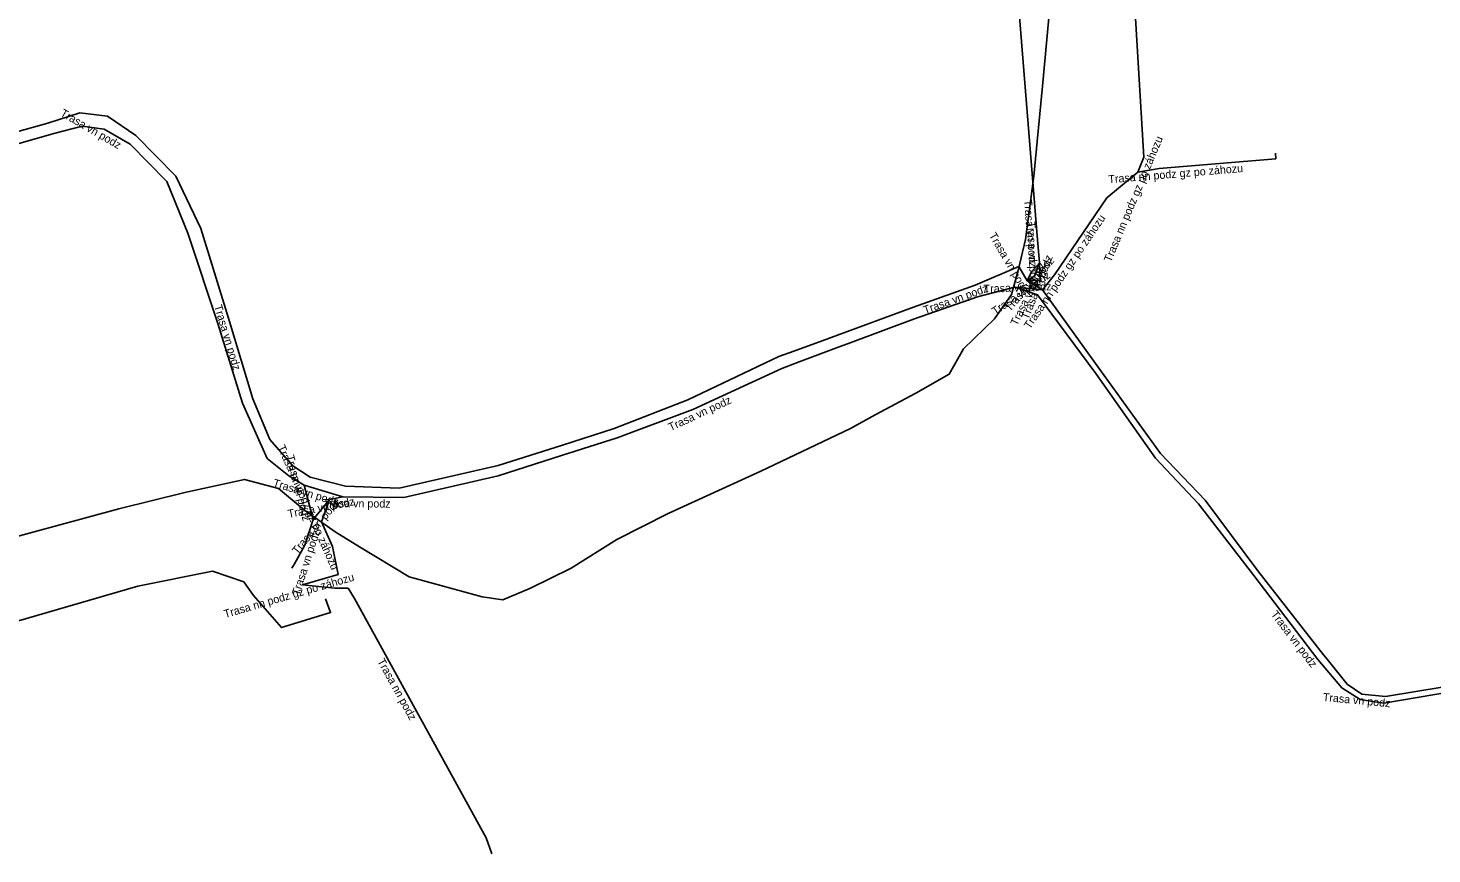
# Model space of a CAD drawing. Extents: x -651117 to -650186, y -983707 to -983198.
# Drawn here: x -650649.4 to -650561.7, y -983536.1 to -983484.5 of the extents above; entities that cross this region are included whole.
import ezdxf

# ---------------------------------------------------------------- set-up
doc = ezdxf.new("R2010")
doc.units = 0
for name, color, linetype in [('Popiskový text - Ostatní atributy Trasy', 7, 'Continuous'), ('Spojnice NN', 7, 'Continuous'), ('Spojnice VN', 7, 'Continuous')]:
    doc.layers.add(name, color=color, linetype=linetype)

msp = doc.modelspace()

# ---------------------------------------------------------------- linework, layer by layer
at = {"layer": 'Spojnice NN'}
for points in [[(-650580.93, -983471.76), (-650579.67, -983492.6)], [(-650580.93, -983471.76), (-650579.67, -983492.6)], [(-650571.458, -983492.343), (-650571.432, -983492.705), (-650578.72, -983493.32), (-650580.06, -983493.53)], [(-650579.67, -983492.6), (-650580.06, -983493.53)], [(-650587.75, -983500.72), (-650586, -983500.89), (-650585.25, -983499.95), (-650581.98, -983495.15), (-650580.06, -983493.53)], [(-650630, -983518.65), (-650630.36, -983516.9), (-650631.04, -983515.36), (-650630.55, -983513.97)], [(-650630.79, -983520.17), (-650630.48, -983521.03), (-650633.55, -983521.97), (-650635.29, -983519.97), (-650635.9, -983519.11), (-650637.85, -983518.45), (-650642.53, -983519.38), (-650659.39, -983524.27), (-650676.94, -983529.34)], [(-650632.24, -983519.3), (-650630, -983518.65)], [(-650632.24, -983519.3), (-650630.22, -983519.5), (-650629.39, -983519.52), (-650628.98, -983520.16), (-650620.77, -983535.09), (-650620.41, -983536.1)]]:
    msp.add_lwpolyline(points, dxfattribs=at)
at = {"layer": 'Spojnice VN'}
for points in [[(-650463.711, -983272.963), (-650439.315, -983305.002), (-650439.764, -983313.686), (-650471.701, -983356.597), (-650494.557, -983376.401), (-650481.039, -983398.986), (-650484.853, -983419.624), (-650488.02, -983430.157), (-650547.138, -983415.267), (-650562.931, -983429.278), (-650562.931, -983445.319), (-650588.398, -983471.931), (-650586.332, -983497.517)], [(-650651.16, -983516.58), (-650643.71, -983514.55), (-650639.59, -983513.54), (-650635.86, -983512.72), (-650633.73, -983513.28), (-650632.1, -983514.63), (-650630.19, -983515.99), (-650628.67, -983516.93), (-650625.58, -983518.8), (-650621.01, -983520.05), (-650619.73, -983520.23), (-650618, -983519.51), (-650615.46, -983518.27), (-650612.6, -983516.47), (-650609.4, -983514.85), (-650603.61, -983512.21), (-650598.01, -983509.55), (-650596.47, -983508.69), (-650593.93, -983507.34), (-650591.83, -983506.16), (-650590.95, -983504.57), (-650589.01, -983502.69), (-650587.95, -983501.17), (-650587.52, -983499.68), (-650587.08, -983497.75), (-650586.54, -983493.78), (-650586, -983488.16), (-650585.29, -983480.51)], [(-650593.782, -983501.869), (-650594.29, -983502.05), (-650598.822, -983503.71), (-650599.779, -983504.061), (-650601.55, -983504.71), (-650602.47, -983505.05), (-650608.16, -983507.75), (-650612.77, -983509.55), (-650615.983, -983510.574), (-650620.02, -983511.86), (-650626.2, -983513.26), (-650629.55, -983513.14), (-650631.76, -983512.58), (-650632.83, -983511.88), (-650634.28, -983510.22), (-650635.34, -983507.7), (-650636.79, -983502.87), (-650638.59, -983497.06), (-650640.15, -983493.78), (-650642.65, -983491.26), (-650644.41, -983490.05), (-650646.14, -983489.84), (-650648.15, -983490.49), (-650653.31, -983491.91)], [(-650632.12, -983513.08), (-650633.08, -983512.5), (-650634.45, -983511.41), (-650635.98, -983507.96), (-650637.53, -983502.98), (-650639.4, -983497.35), (-650640.7, -983494.12), (-650643.01, -983491.79), (-650644.63, -983490.85), (-650645.99, -983490.67), (-650647.77, -983491.12), (-650652.95, -983492.61), (-650662.96, -983495.62), (-650669.43, -983497.54)], [(-650586.332, -983497.517), (-650586.197, -983499.199)], [(-650586.7, -983499.77), (-650586.197, -983499.199)], [(-650586.51, -983500.01), (-650586.197, -983499.199)], [(-650586.197, -983499.199), (-650586.15, -983500.29)], [(-650587.48, -983499.43), (-650590.22, -983500.6), (-650593.782, -983501.869)], [(-650586.96, -983500.32), (-650587.48, -983499.43)], [(-650586.96, -983500.32), (-650586.7, -983499.77)], [(-650586.96, -983500.32), (-650586.51, -983500.01)], [(-650587.75, -983500.72), (-650590.07, -983501.32), (-650594.06, -983502.71), (-650598.032, -983504.19), (-650598.879, -983504.505), (-650601.2, -983505.37), (-650602.3, -983505.8), (-650607.85, -983508.36), (-650612.57, -983510.12), (-650616.055, -983511.23), (-650620.01, -983512.49), (-650625.91, -983513.84)], [(-650542.63, -983528.14), (-650546.61, -983528.01), (-650548.08, -983527.44), (-650549.49, -983526.01), (-650550.33, -983525.21), (-650551.45, -983524.77), (-650557.21, -983525.43), (-650564.69, -983526.69), (-650566.17, -983526.46), (-650567.31, -983525.74), (-650568.116, -983524.784), (-650568.81, -983523.96), (-650572.81, -983518.71), (-650576.26, -983514.24), (-650578.95, -983511.4), (-650582.67, -983506.11), (-650586.31, -983501.2), (-650587.75, -983500.72)], [(-650586.96, -983500.32), (-650586.15, -983500.29)], [(-650532.88, -983530.14), (-650537.74, -983528.5), (-650541.5, -983527.76), (-650546.42, -983527.69), (-650547.96, -983527.14), (-650549.18, -983525.77), (-650550.2, -983524.72), (-650551.38, -983524.41), (-650557.26, -983525.07), (-650564.59, -983526.27), (-650566.05, -983526.13), (-650566.98, -983525.51), (-650568.234, -983523.941), (-650568.45, -983523.67), (-650572.56, -983518.43), (-650575.85, -983514.01), (-650578.63, -983511.11), (-650582.42, -983505.85), (-650586, -983500.89), (-650586.96, -983500.32)], [(-650629.72, -983513.81), (-650632.12, -983513.08)], [(-650631.57, -983515.22), (-650632.12, -983513.08)], [(-650631.57, -983515.22), (-650630.55, -983513.97)], [(-650629.72, -983513.81), (-650630.55, -983513.97)], [(-650625.91, -983513.84), (-650629.72, -983513.81)], [(-650632.892, -983518.262), (-650632.74, -983518), (-650632.09, -983516.82), (-650631.57, -983515.22)]]:
    msp.add_lwpolyline(points, dxfattribs=at)

# ---------------------------------------------------------------- texts
at = {"layer": 'Popiskový text - Ostatní atributy Trasy'}
for s, rotation, p in [('Trasa vn podz', 329.87568, (-650647.406, -983489.991)), ('Trasa nn podz gz po záhozu', 67.24902, (-650581.732, -983499.198)), ('Trasa nn podz gz po záhozu', 4.82349, (-650581.871, -983494.238)), ('Trasa vn podz', 274.6142, (-650587.165, -983495.273)), ('Trasa nn podz gz po záhozu', 55.73535, (-650586.795, -983503.373)), ('Trasa vn podz', 272.45366, (-650586.958, -983496.628)), ('Trasa vn podz', 300.29645, (-650589.369, -983497.485)), ('Trasa vn podz', 48.60871, (-650588.042, -983502.276)), ('Trasa vn podz', 64.69862, (-650587.587, -983503.169)), ('Trasa vn podz', 68.88087, (-650586.881, -983502.775)), ('Trasa vn podz', 34.56252, (-650588.958, -983502.486)), ('Trasa vn podz', 19.60942, (-650593.344, -983502.403)), ('Trasa vn podz', 2.1211, (-650589.676, -983501.071)), ('Trasa vn podz', 286.71013, (-650637.761, -983501.896)), ('Trasa vn podz', 24.76205, (-650609.24, -983509.716)), ('Trasa nn podz gz po záhozu', 293.82426, (-650633.808, -983510.702)), ('Trasa vn podz', 284.4136, (-650633.258, -983511.264)), ('Trasa vn podz', 343.08199, (-650634.12, -983513.151)), ('Trasa vn podz', 10.91113, (-650633.102, -983515.124)), ('Trasa vn podz', 50.78555, (-650632.546, -983517.445)), ('Trasa vn podz', 359.54886, (-650630.968, -983514.45)), ('Trasa vn podz', 71.99584, (-650632.44, -983519.999)), ('Trasa nn podz gz po záhozu', 16.1816, (-650637.065, -983521.377)), ('Trasa vn podz', 307.30395, (-650571.77, -983521.147)), ('Trasa nn podz', 298.80637, (-650627.575, -983524.063)), ('Trasa vn podz', 354.52263, (-650568.513, -983526.546))]:
    msp.add_text(s, height=0.5, rotation=rotation, dxfattribs=at).set_placement(p)

doc.saveas('drawing.dxf')
